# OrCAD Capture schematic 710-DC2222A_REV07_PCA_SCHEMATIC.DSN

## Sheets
1 PAGE3: size Custom; note: OVERSAMPLED 32-BIT ADC WITH PROGRAMMABLE DIGITAL FILTER
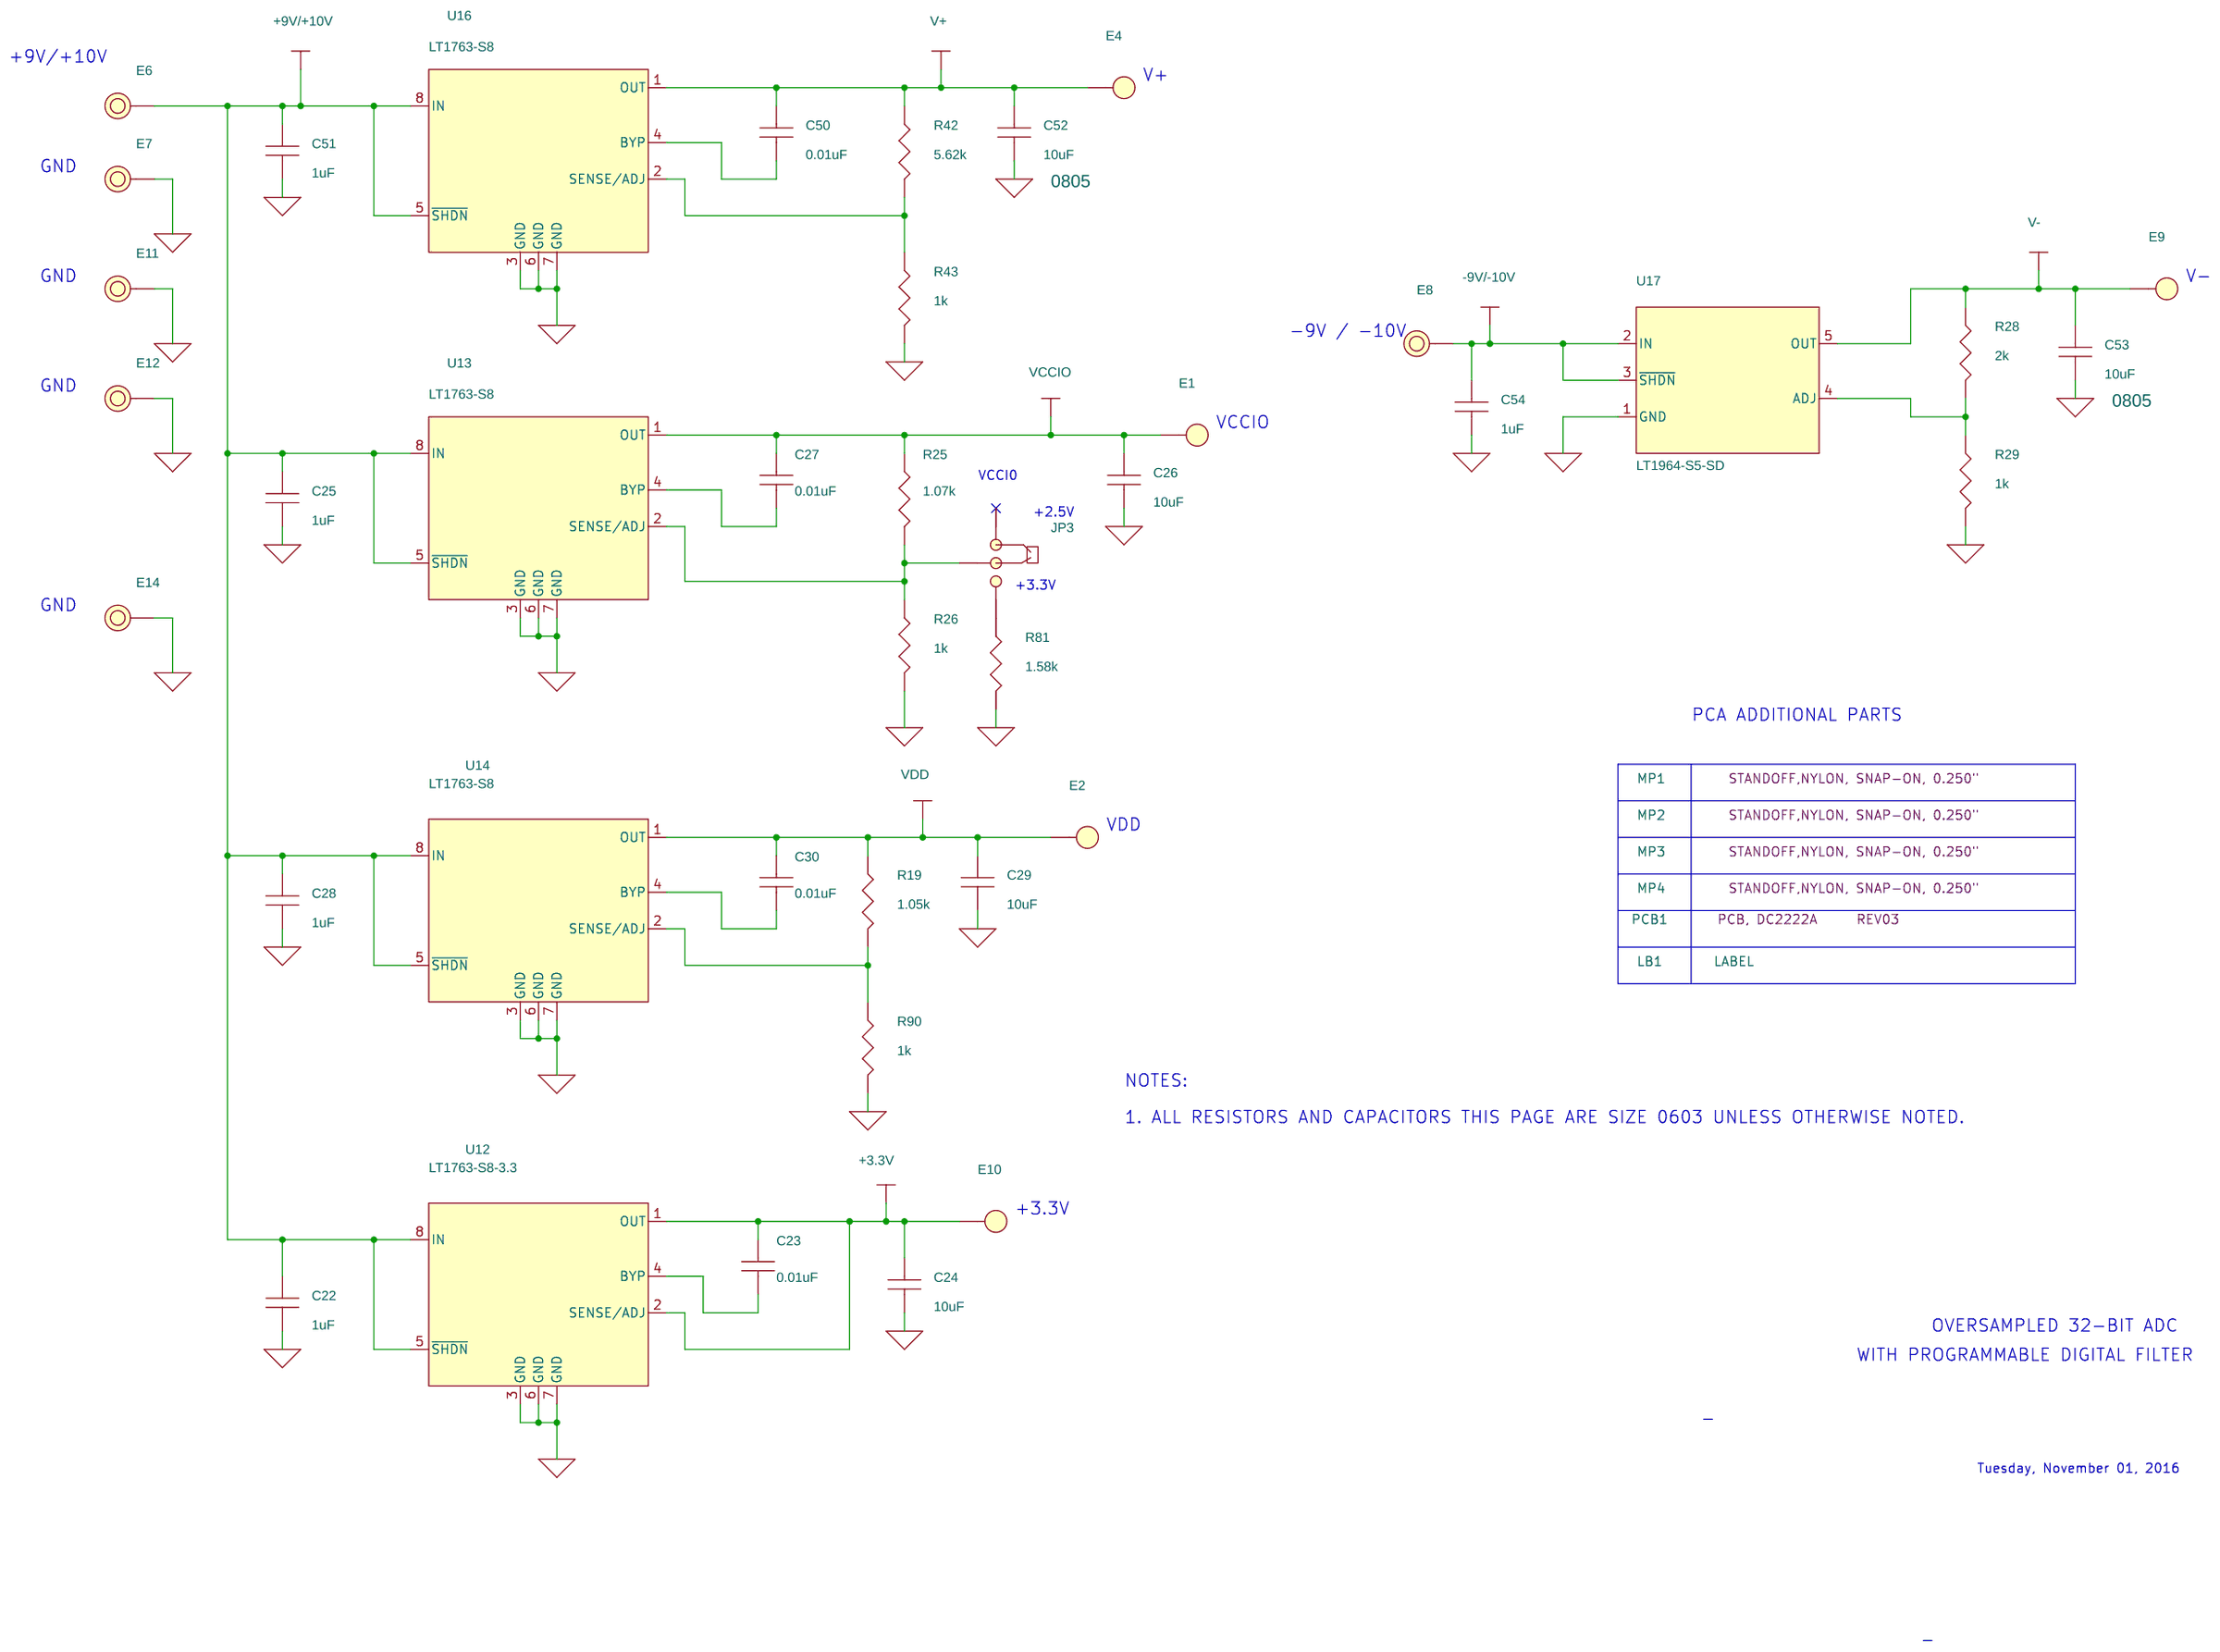
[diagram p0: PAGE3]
2 PAGE2: size Custom
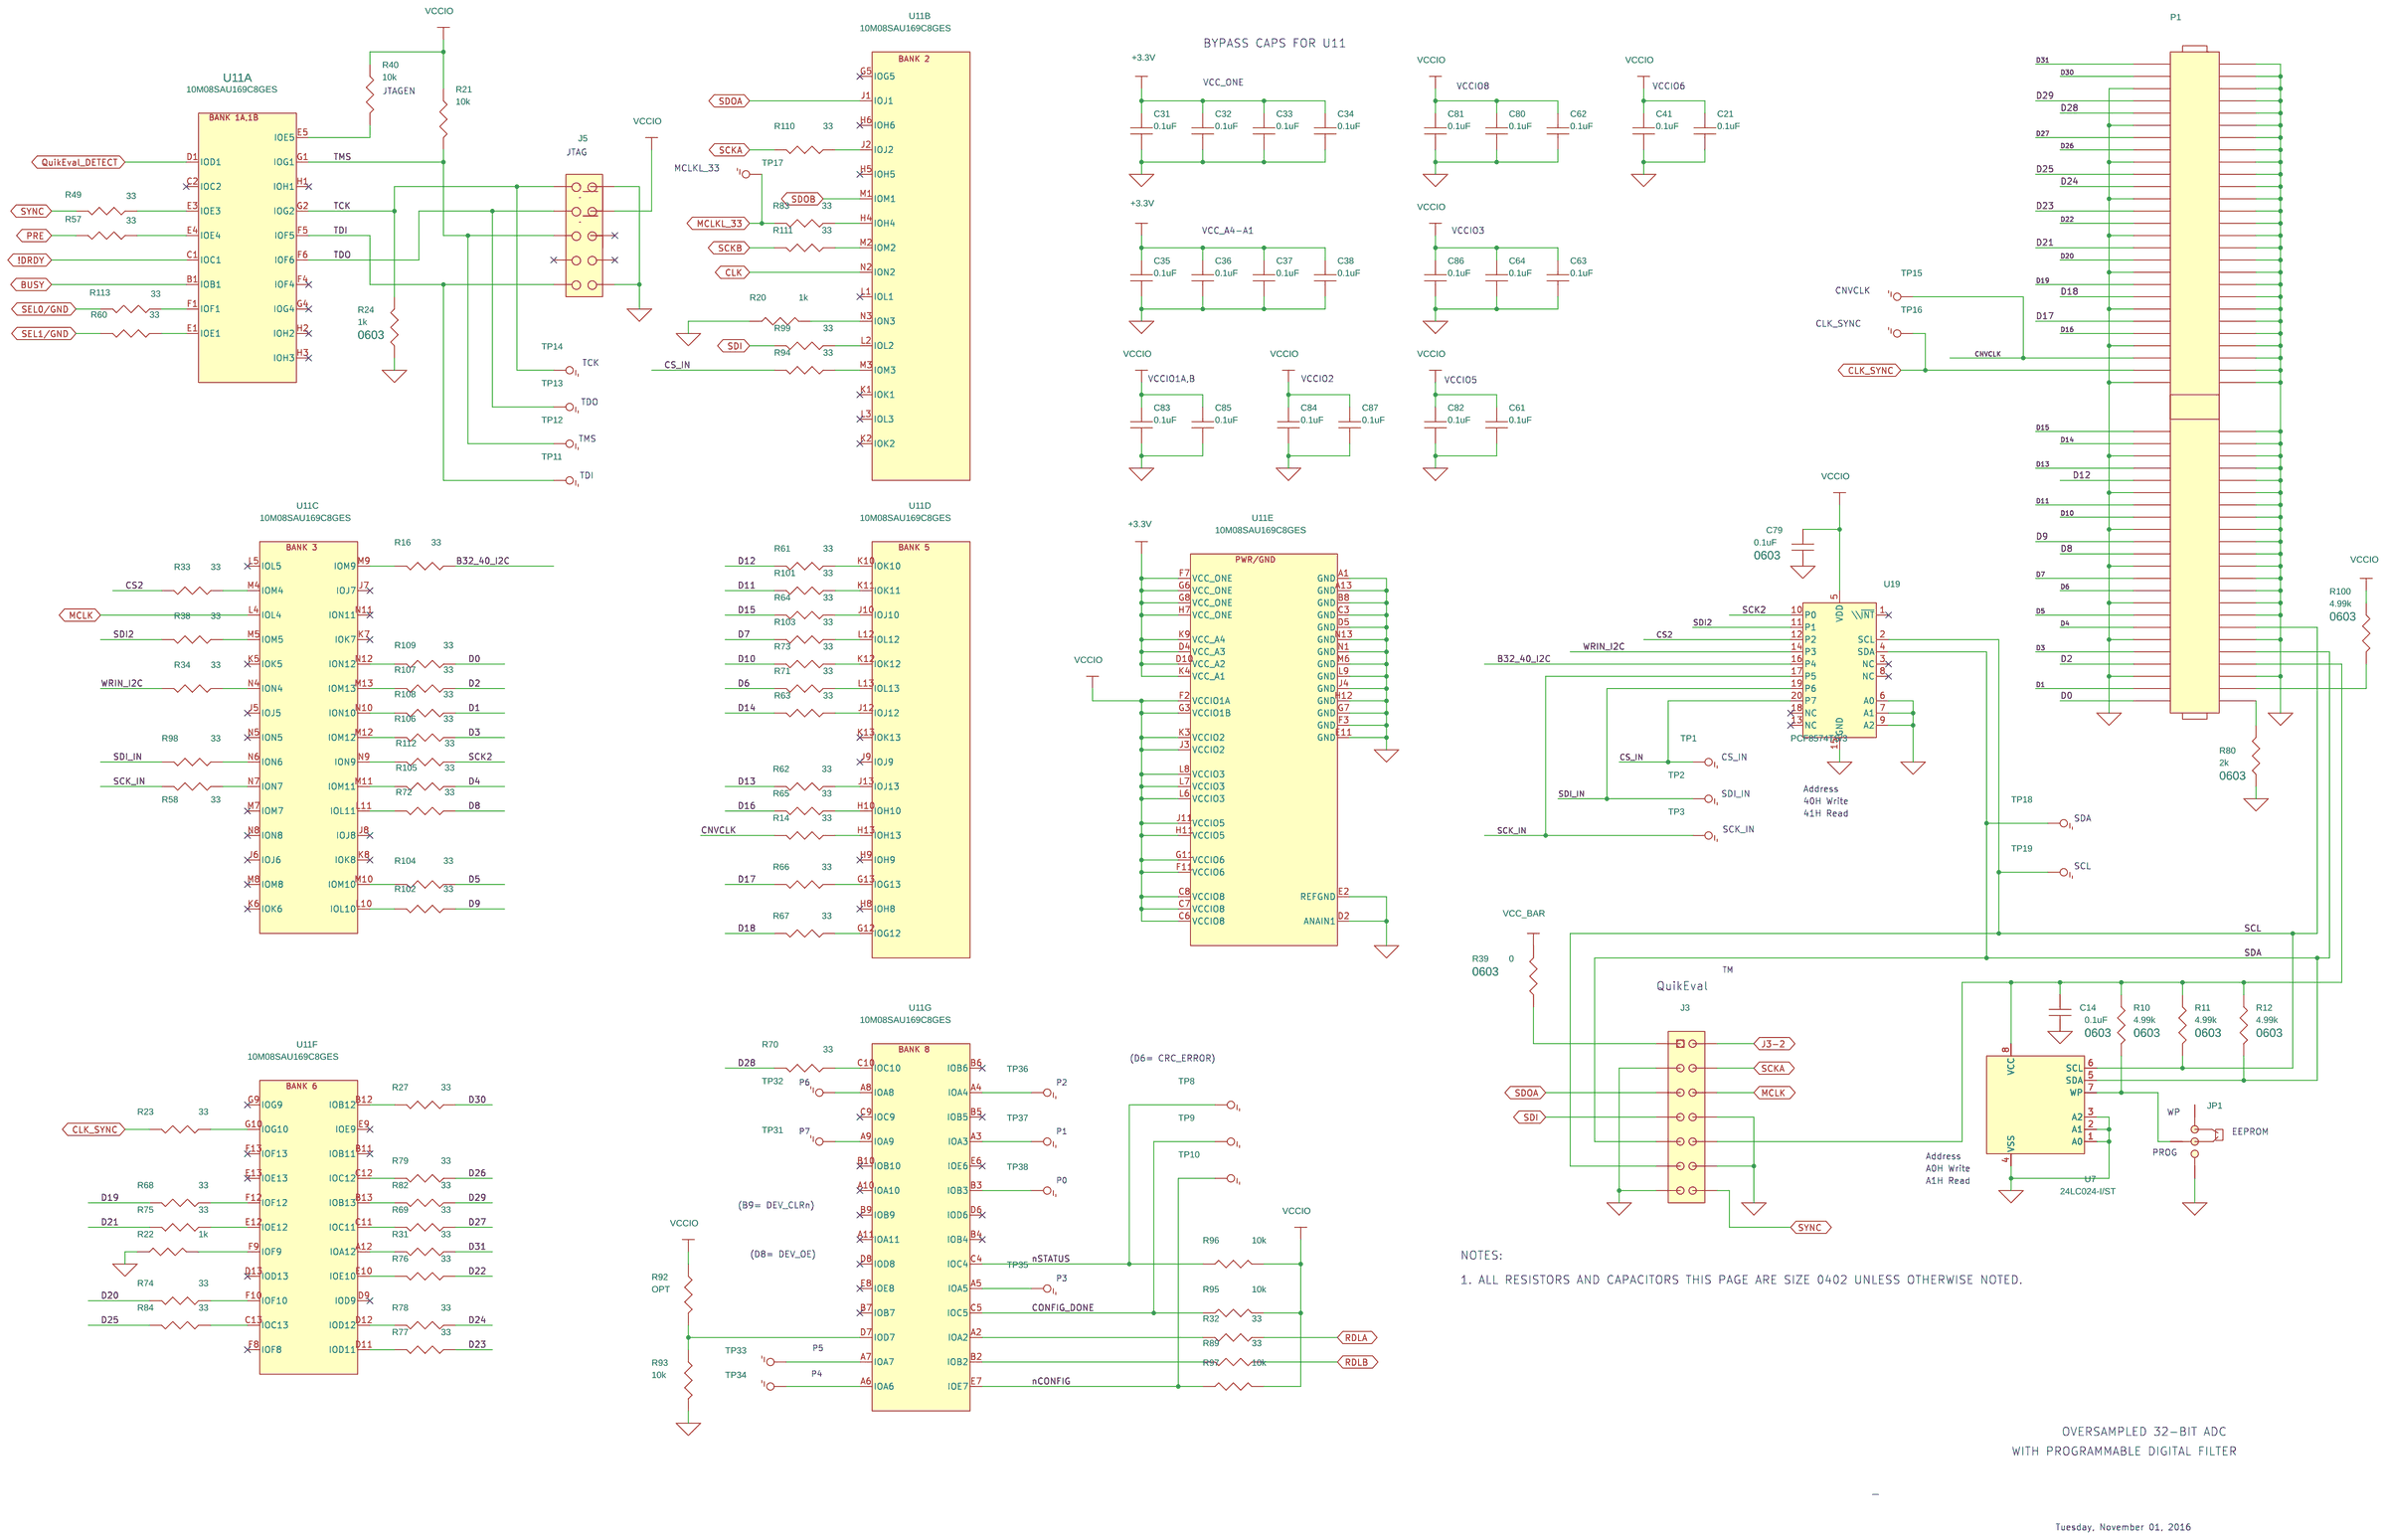
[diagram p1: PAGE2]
3 PAGE1: size Custom
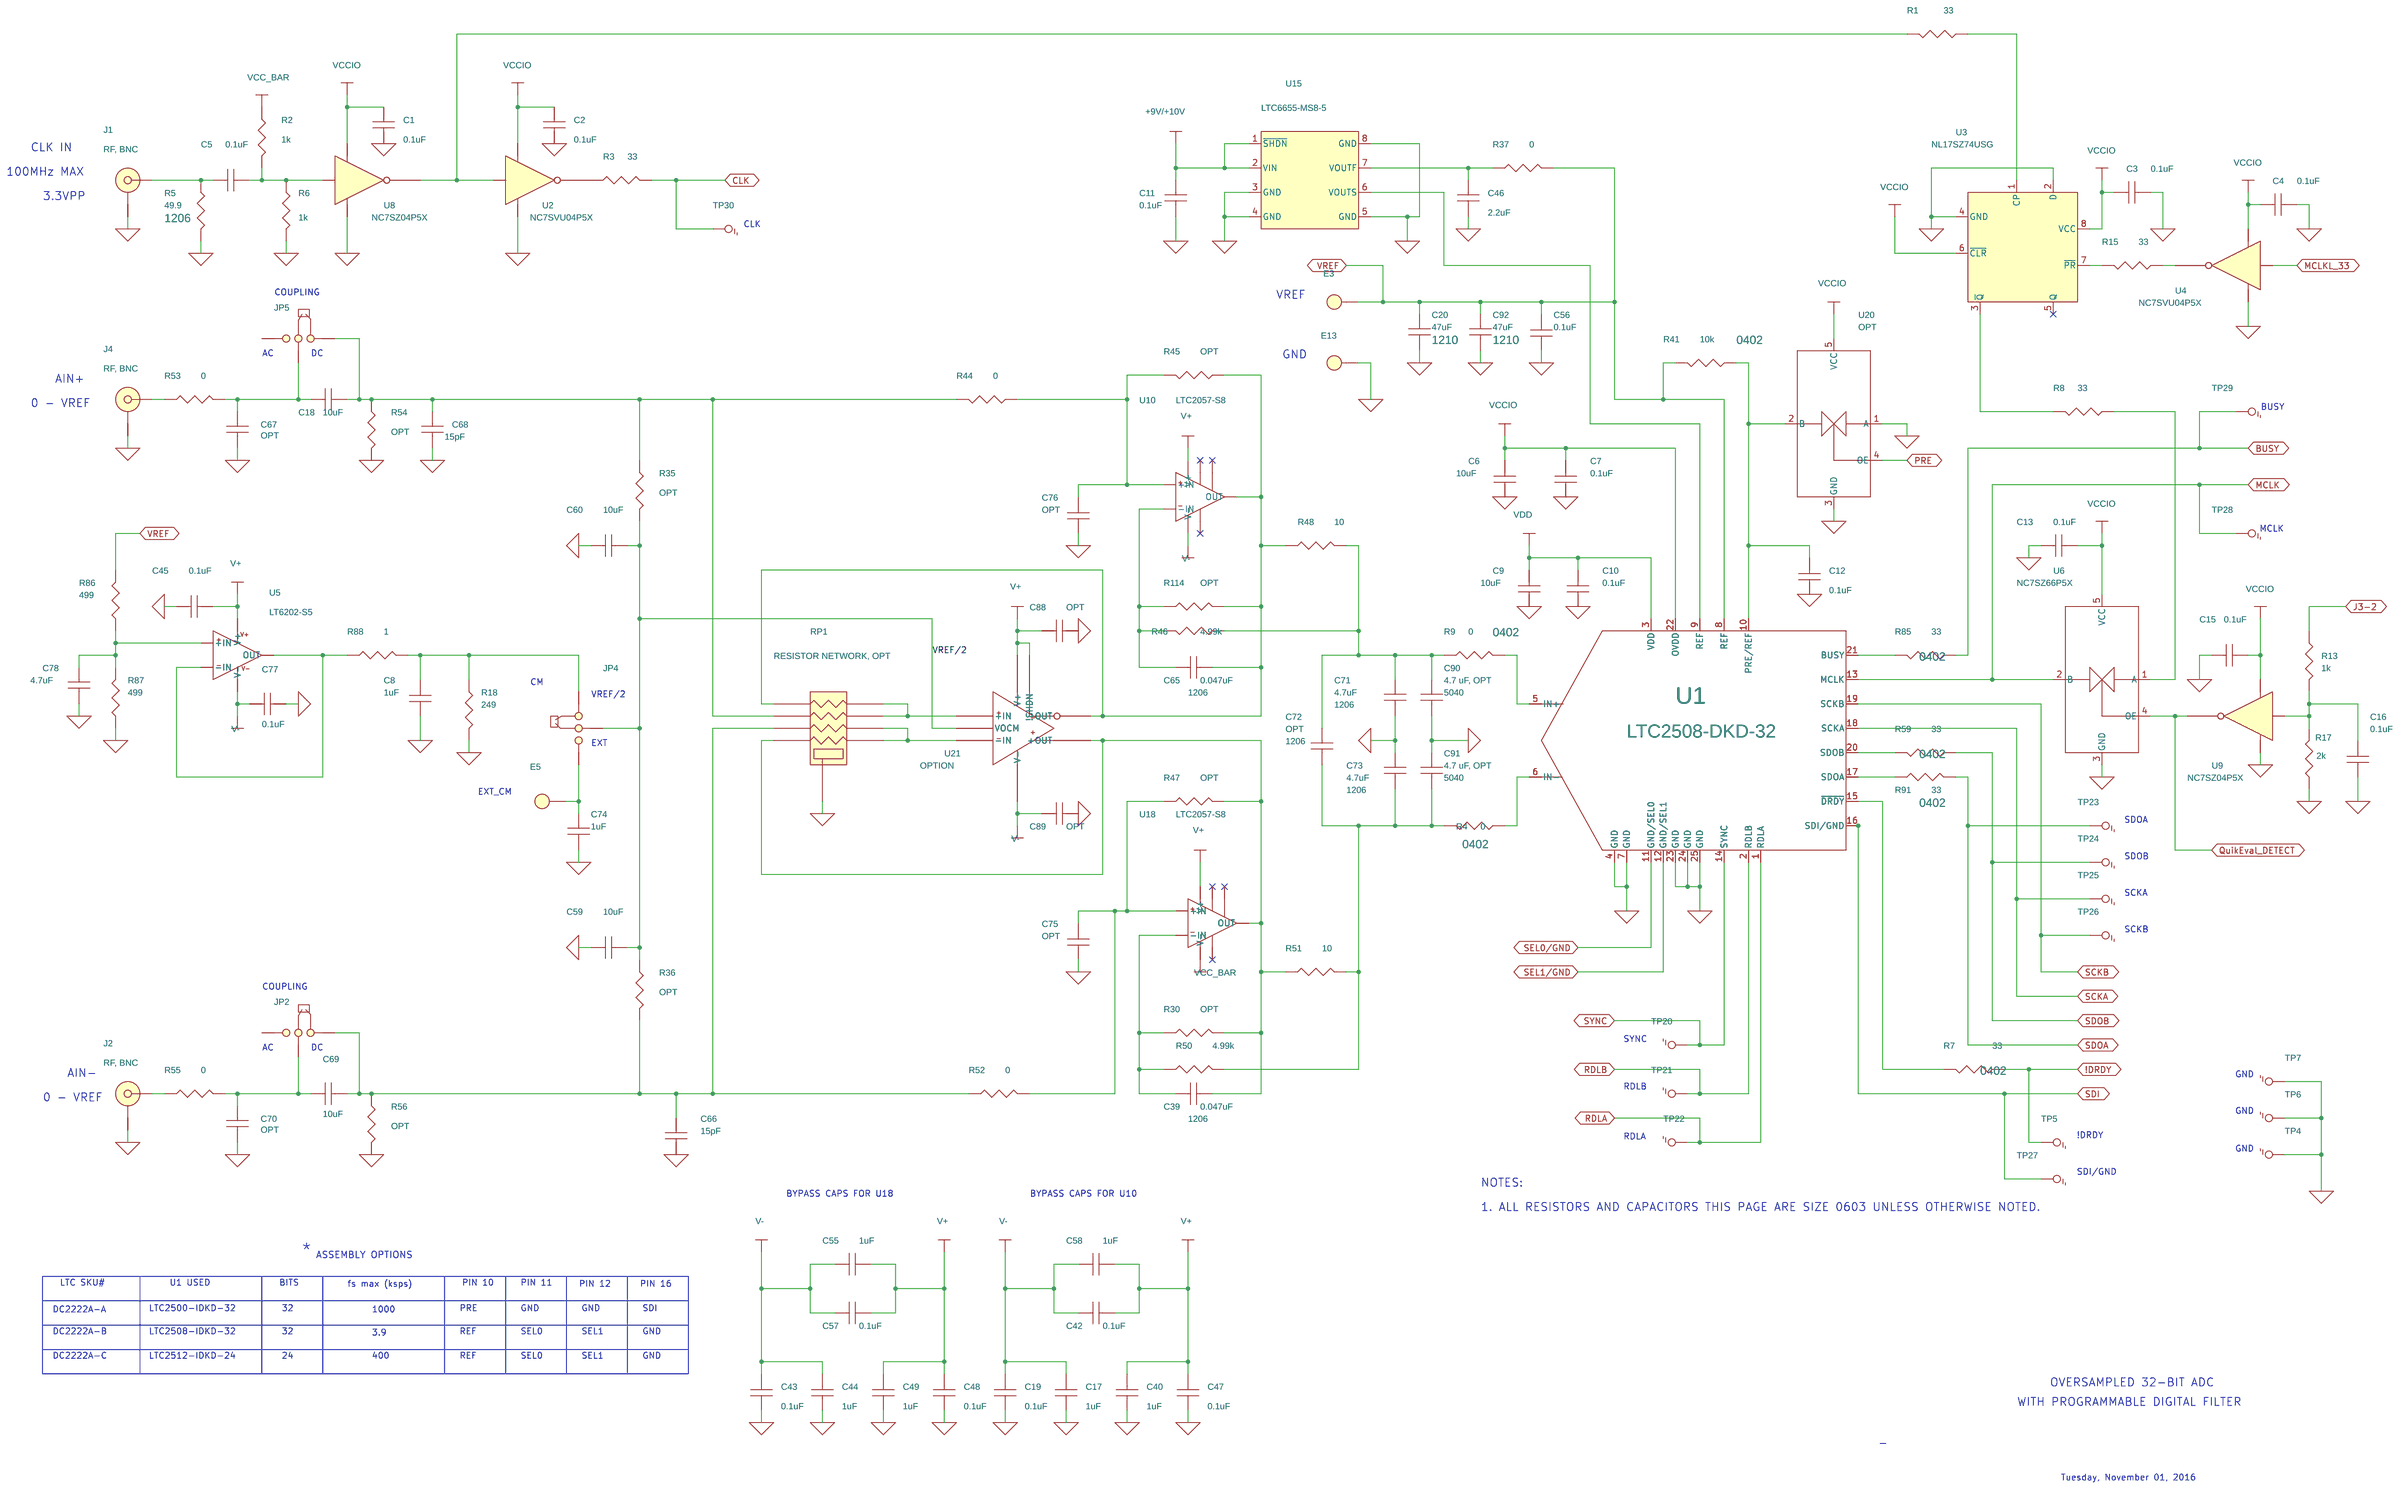
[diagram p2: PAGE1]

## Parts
sheet PAGE1
C1  0.1uF  [CC0603L]
C2  0.1uF  [CC0603L]
C3  0.1uF  [CC0603L]
C4  0.1uF  [CC0603L]
C5  0.1uF  [CC0603L]
C6  10uF  [CC0603L]
C7  0.1uF  [CC0603L]
C8  1uF  [CC0603L]
C9  10uF  [CC0603L]
C10  0.1uF  [CC0603L]
C11  0.1uF  [CC0603L]
C12  0.1uF  [CC0603L]
C13  0.1uF  [CC0603L]
C15  0.1uF  [CC0603L]
C16  0.1uF  [CC0603L]
C17  1uF  [CC0603N]
C18  10uF  [CC0603L]
C19  0.1uF  [CC0603N]
C20  47uF  [CC1210N]
C39  0.047uF  [CC1206N]
C40  1uF  [CC0603N]
C42  0.1uF  [CC0603N]
C43  0.1uF  [CC0603N]
C44  1uF  [CC0603N]
C45  0.1uF  [CC0603L]
C46  2.2uF  [CC0603L]
C47  0.1uF  [CC0603N]
C48  0.1uF  [CC0603N]
C49  1uF  [CC0603N]
C55  1uF  [CC0603N]
C56  0.1uF  [CC0603L]
C57  0.1uF  [CC0603N]
C58  1uF  [CC0603N]
C59  10uF  [CC0603N]
C60  10uF  [CC0603N]
C65  0.047uF  [CC1206N]
C66  15pF  [CC0603N]
C67  OPT  [CC1206N]
C68  15pF  [CC0603L]
C69  10uF  [CC0603L]
C70  OPT  [CC1206N]
C71  4.7uF  [CC1206N]
C72  OPT  [CC1206N]
C73  4.7uF  [CC1206N]
C74  1uF  [CC0603L]
C75  OPT  [CC0603N]
C76  OPT  [CC0603N]
C77  0.1uF  [CC0603L]
C78  4.7uF  [CC0603N]
C88  OPT  [CC0603L]
C89  OPT  [CC0603L]
C90  4.7 uF, OPT  [WIMA_5040]
C91  4.7 uF, OPT  [WIMA_5040]
C92  47uF  [CC1210N]
E3  TEST POINT  [MILLMAX2308]
E5  TEST POINT  [MILLMAX2308]
E13  TEST POINT  [MILLMAX2308]
J1  RF, BNC  [CONNEX-112404]
J2  RF, BNC  [CONNEX-112404]
J4  RF, BNC  [CONNEX-112404]
JP2  HDR.  [JP3X1/100]
JP4  HDR.  [JP3X1/100]
JP5  HDR.  [JP3X1/100]
R1  33  [CR0603L]
R2  1k  [CR0603L]
R3  33  [CR0603L]
R4  0  [CR0402L]
R5  49.9  [CR1206N]
R6  1k  [CR0603L]
R7  33  [CR0402L]
R8  33  [CR0603L]
R9  0  [CR0402L]
R13  1k  [CR0603L]
R15  33  [CR0603L]
R17  2k  [CR0603L]
R18  249  [CR0603L]
R30  OPT  [CR0603N]
R35  OPT  [CR0603N]
R36  OPT  [CR0603N]
R37  0  [CR0603L]
R41  10k  [CR0402N]
R44  0  [CR0603N]
R45  OPT  [CR0603N]
R46  4.99k  [CR0603N]
R47  OPT  [CR0603N]
R48  10  [CR0603N]
R50  4.99k  [CR0603N]
R51  10  [CR0603N]
R52  0  [CR0603N]
R53  0  [CR0603L]
R54  OPT  [CR0603N]
R55  0  [CR0603L]
R56  OPT  [CR0603N]
R59  33  [CR0402L]
R85  33  [CR0402L]
R86  499  [CR0603N]
R87  499  [CR0603N]
R88  1  [CR0603N]
R91  33  [CR0402L]
R114  OPT  [CR0603N]
RP1  RESISTOR NETWORK, OPT  [LTC-MS8E]
TP4  COPPER FEATURE PAD  [PADSTYLE1]
TP5  COPPER FEATURE PAD  [PADSTYLE1]
TP6  COPPER FEATURE PAD  [PADSTYLE1]
TP7  COPPER FEATURE PAD  [PADSTYLE1]
TP20  COPPER FEATURE PAD  [PADSTYLE1]
TP21  COPPER FEATURE PAD  [PADSTYLE1]
TP22  COPPER FEATURE PAD  [PADSTYLE1]
TP23  COPPER FEATURE PAD  [PADSTYLE1]
TP24  COPPER FEATURE PAD  [PADSTYLE1]
TP25  COPPER FEATURE PAD  [PADSTYLE1]
TP26  COPPER FEATURE PAD  [PADSTYLE1]
TP27  COPPER FEATURE PAD  [PADSTYLE1]
TP28  COPPER FEATURE PAD  [PADSTYLE1]
TP29  COPPER FEATURE PAD  [PADSTYLE1]
TP30  COPPER FEATURE PAD  [PADSTYLE1]
U1  LTC2508-DKD-32  [LTC-DKD-24-1864]
U2  NC7SVU04P5X  [SC70-5]
U3  NL17SZ74USG  [ONSEMI-US8]
U4  NC7SVU04P5X  [SC70-5]
U5  LT6202-S5  [LTC-S5-5-1635]
U6  NC7SZ66P5X  [SC70-5]
U8  NC7SZ04P5X  [SC70-5]
U9  NC7SZ04P5X  [SC70-5]
U10  LTC2057-S8  [LTC-S8-8-1610(S8)]
U15  LTC6655-MS8-5  [LTC-MS8-8-1660]
U18  LTC2057-S8  [LTC-S8-8-1610(S8)]
U20  OPT  [SC70-5]
U21  OPTION  [LTC-MS8-8-1660]
XJP2  SHUNT
XJP4  SHUNT
XJP5  SHUNT
sheet PAGE2
C14  0.1uF  [CC0603L]
C21  0.1uF  [CC0402L]
C31  0.1uF  [CC0402L]
C32  0.1uF  [CC0402L]
C33  0.1uF  [CC0402L]
C34  0.1uF  [CC0402L]
C35  0.1uF  [CC0402L]
C36  0.1uF  [CC0402L]
C37  0.1uF  [CC0402L]
C38  0.1uF  [CC0402L]
C41  0.1uF  [CC0402L]
C61  0.1uF  [CC0402L]
C62  0.1uF  [CC0402L]
C63  0.1uF  [CC0402L]
C64  0.1uF  [CC0402L]
C79  0.1uF  [CC0603L]
C80  0.1uF  [CC0402L]
C81  0.1uF  [CC0402L]
C82  0.1uF  [CC0402L]
C83  0.1uF  [CC0402L]
C84  0.1uF  [CC0402L]
C85  0.1uF  [CC0402L]
C86  0.1uF  [CC0402L]
C87  0.1uF  [CC0402L]
J3  HDR.  [HD2X7-079-MOLEX]
J5  HDR.  [SAMTEC_TSW-105-07-L-D]
JP1  HDR.  [JP3X1/100]
P1  EDGE-CON-100  [SMTC_EDG_CONN_100]
R10  4.99k  [CR0603L]
R11  4.99k  [CR0603L]
R12  4.99k  [CR0603L]
R14  33  [CR0402L]
R16  33  [CR0402L]
R20  1k  [CR0402L]
R21  10k  [CR0402L]
R22  1k  [CR0402L]
R23  33  [CR0402L]
R24  1k  [CR0603N]
R27  33  [CR0402L]
R31  33  [CR0402L]
R32  33  [CR0402L]
R33  33  [CR0402L]
R34  33  [CR0402L]
R38  33  [CR0402L]
R39  0  [CR0603N]
R40  10k  [CR0402L]
R49  33  [CR0402L]
R57  33  [CR0402L]
R58  33  [CR0402L]
R60  33  [CR0402L]
R61  33  [CR0402L]
R62  33  [CR0402L]
R63  33  [CR0402L]
R64  33  [CR0402L]
R65  33  [CR0402L]
R66  33  [CR0402L]
R67  33  [CR0402L]
R68  33  [CR0402L]
R69  33  [CR0402L]
R70  33  [CR0402L]
R71  33  [CR0402L]
R72  33  [CR0402L]
R73  33  [CR0402L]
R74  33  [CR0402L]
R75  33  [CR0402L]
R76  33  [CR0402L]
R77  33  [CR0402L]
R78  33  [CR0402L]
R79  33  [CR0402L]
R80  2k  [CR0603N]
R82  33  [CR0402L]
R83  33  [CR0402L]
R84  33  [CR0402L]
R89  33  [CR0402L]
R92  OPT  [CR0402N]
R93  10k  [CR0402N]
R94  33  [CR0402L]
R95  10k  [CR0402N]
R96  10k  [CR0402N]
R97  10k  [CR0402N]
R98  33  [CR0402L]
R99  33  [CR0402L]
R100  4.99k  [CR0603N]
R101  33  [CR0402L]
R102  33  [CR0402L]
R103  33  [CR0402L]
R104  33  [CR0402L]
R105  33  [CR0402L]
R106  33  [CR0402L]
R107  33  [CR0402L]
R108  33  [CR0402L]
R109  33  [CR0402L]
R110  33  [CR0402L]
R111  33  [CR0402L]
R112  33  [CR0402L]
R113  33  [CR0402L]
TP1  COPPER FEATURE PAD  [PADSTYLE1]
TP2  COPPER FEATURE PAD  [PADSTYLE1]
TP3  COPPER FEATURE PAD  [PADSTYLE1]
TP8  COPPER FEATURE PAD  [PADSTYLE1]
TP9  COPPER FEATURE PAD  [PADSTYLE1]
TP10  COPPER FEATURE PAD  [PADSTYLE1]
TP11  COPPER FEATURE PAD  [PADSTYLE1]
TP12  COPPER FEATURE PAD  [PADSTYLE1]
TP13  COPPER FEATURE PAD  [PADSTYLE1]
TP14  COPPER FEATURE PAD  [PADSTYLE1]
TP15  COPPER FEATURE PAD  [PADSTYLE1]
TP16  COPPER FEATURE PAD  [PADSTYLE1]
TP17  COPPER FEATURE PAD  [PADSTYLE1]
TP18  COPPER FEATURE PAD  [PADSTYLE1]
TP19  COPPER FEATURE PAD  [PADSTYLE1]
TP31  COPPER FEATURE PAD  [PADSTYLE1]
TP32  COPPER FEATURE PAD  [PADSTYLE1]
TP33  COPPER FEATURE PAD  [PADSTYLE1]
TP34  COPPER FEATURE PAD  [PADSTYLE1]
TP35  COPPER FEATURE PAD  [PADSTYLE1]
TP36  COPPER FEATURE PAD  [PADSTYLE1]
TP37  COPPER FEATURE PAD  [PADSTYLE1]
TP38  COPPER FEATURE PAD  [PADSTYLE1]
U7  24LC024-I/ST  [MICROCHIP-TSSOP-8]
U11  10M08SAU169C8GES  [ALTERA-169UBGA]  (sections A,B,C,D,E,F,G)
U19  PCF8574TS/3  [JEDEC-MO-152]
XJP1  SHUNT
sheet PAGE3
C22  1uF  [CC0603L]
C23  0.01uF  [CC0603L]
C24  10uF  [CC0603L]
C25  1uF  [CC0603L]
C26  10uF  [CC0603L]
C27  0.01uF  [CC0603L]
C28  1uF  [CC0603L]
C29  10uF  [CC0603L]
C30  0.01uF  [CC0603L]
C50  0.01uF  [CC0603L]
C51  1uF  [CC0603L]
C52  10uF  [CC0805N]
C53  10uF  [CC0805N]
C54  1uF  [CC0603L]
E1  TEST POINT  [MILLMAX2308]
E2  TEST POINT  [MILLMAX2308]
E4  TEST POINT  [MILLMAX2308]
E6  TEST POINT  [MILLMAX2501]
E7  TEST POINT  [MILLMAX2501]
E8  TEST POINT  [MILLMAX2501]
E9  TEST POINT  [MILLMAX2308]
E10  TEST POINT  [MILLMAX2308]
E11  TEST POINT  [MILLMAX2501]
E12  TEST POINT  [MILLMAX2501]
E14  TEST POINT  [MILLMAX2501]
JP3  HDR.  [JP3X1/100]
LB1  LABEL  [895-0154_REV01]
MP1  STANDOFF  [MTG-8831]
MP2  STANDOFF  [MTG-8831]
MP3  STANDOFF  [MTG-8831]
MP4  STANDOFF  [MTG-8831]
PCB1  PCB FABRICATION
R19  1.05k  [CR0603N]
R25  1.07k  [CR0603L]
R26  1k  [CR0603L]
R28  2k  [CR0603L]
R29  1k  [CR0603L]
R42  5.62k  [CR0603L]
R43  1k  [CR0603L]
R81  1.58k  [CR0603N]
R90  1k  [CR0603L]
U12  LT1763-S8-3.3  [LTC-S8-8-1610(S8)]
U13  LT1763-S8  [LTC-S8-8-1610(S8)]
U14  LT1763-S8  [LTC-S8-8-1610(S8)]
U16  LT1763-S8  [LTC-S8-8-1610(S8)]
U17  LT1964-S5-SD  [LTC-S5-5-1635]
XJP3  SHUNT

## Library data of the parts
C1-C5 C7 C10 C11 C13-C16 C56 C79 = CAP: CAP.,0.1uF,X7R,16V,10%,0603; CLASS: DISCRETE; Dielectric Type: X7R; FPLIST: CC0603N,CC0603L,CC0603M; Manufacturer: AVX; Manufacturer PN: 0603YC104KAT2A; PART_NUMBER: 150-0164; Package Size: 0603; Package Type: SMD; Rated Voltage: 16V; Tolerance: 10%
C6 C9 C18 C24 C26 C29 C69 = CAP: CAP.,10uF,X5R,6.3V,20%,0603; CLASS: DISCRETE; Dielectric Type: X5R; FPLIST: CC0603N,CC0603L,CC0603M; Manufacturer: AVX; Manufacturer PN: 06036D106MAT2A; PART_NUMBER: 150-3401; Package Size: 0603; Package Type: SMD; Rated Voltage: 6.3V; Tolerance: 20%
C8 = CAP: CAP.,1uF,X7R,16V,10%,0603; CLASS: DISCRETE; Dielectric Type: X7R; FPLIST: CC0603N,CC0603L,CC0603M; Manufacturer: AVX; Manufacturer PN: 0603YC105KAT2A; PART_NUMBER: 150-3384; Package Size: 0603; Package Type: SMD; Rated Voltage: 16V; Tolerance: 10%
C12 C19 C42 C43 C45 C47 C48 C57 C77 = CAP: CAP.,0.1uF,X7R,25V,20%,0603; CLASS: DISCRETE; Dielectric Type: X7R; FPLIST: CC0603N,CC0603L,CC0603M; Manufacturer: MURATA; Manufacturer PN: GRM188R71E104MA01D; PART_NUMBER: 150-3402; Package Size: 0603; Package Type: SMD; Rated Voltage: 25V; Tolerance: 20%
C17 C22 C25 C28 C40 C44 C49 C51 C54 C55 C58 C74 = CAP: CAP.,1uF,X7R,25V,10%,0603; CLASS: DISCRETE; Dielectric Type: X7R; FPLIST: CC0603N,CC0603L,CC0603M; Manufacturer: TDK; Manufacturer PN: C1608X7R1E105K080AB; PART_NUMBER: 150-3372; Package Size: 0603; Package Type: SMD; Rated Voltage: 25V; Tolerance: 10%
C20 C92 = CAP: CAP.,47uF,X7R,10V,10%,1210; CLASS: DISCRETE; Dielectric Type: X7R; Manufacturer: MURATA; Manufacturer PN: GRM32ER71A476KE15L; PART_NUMBER: 150-3403; Package Size: 1210; Package Type: SMD; Rated Voltage: 10V; Tolerance: 10%
C39 C65 = CAP: CAP.,0.047uF,C0G,50V,5%,1206; CLASS: DISCRETE; FPLIST: CC1206N,CC1206L,CC1206M; PART_NUMBER: 150-0469; Package Size: 1206; Package Type: Surface Mount, MLCC
C46 = CAP: CAP.,2.2uF,X5R,10V,10%,0603; CLASS: DISCRETE; Dielectric Type: X5R; FPLIST: CC0603N,CC0603L,CC0603M; Manufacturer: MURATA; Manufacturer PN: GRM188R61A225KE34D; PART_NUMBER: 150-0168; Package Size: 0603; Package Type: SMD; Rated Voltage: 10V; Tolerance: 10%
C59 C60 = CAP: CAP.,10uF,X5R,6.3V,20%,0603; CLASS: DISCRETE; Dielectric Type: X5R; Manufacturer: AVX; Manufacturer PN: 06036D106MAT2A; PART_NUMBER: 150-3401; Package Size: 0603; Package Type: SMD; Rated Voltage: 6.3V; Tolerance: 20%
C66 = CAP: CAP.,15pF,C0G,50V,10%,0603; CLASS: DISCRETE; Dielectric Type: C0G; Manufacturer: KEMET; Manufacturer PN: C0603C150K5GAC7867; PART_NUMBER: 150-3185; Package Size: 0603; Package Type: SMD; Rated Voltage: 50V; Tolerance: 10%
C67 C70 C72 = CAP: CAP., OPTION, 1206; CLASS: DISCRETE; FPLIST: CC1206N,CC1206L,CC1206M; PART_NUMBER: 150-3160; Package Size: 1206; Package Type: SMD
C68 = CAP: CAP.,15pF,C0G,50V,10%,0603; CLASS: DISCRETE; Dielectric Type: C0G; FPLIST: CC0603N,CC0603L,CC0603M; Manufacturer: KEMET; Manufacturer PN: C0603C150K5GAC7867; PART_NUMBER: 150-3185; Package Size: 0603; Package Type: SMD; Rated Voltage: 50V; Tolerance: 10%
C71 C73 = CAP: CAP.,4.7uF,X7R,25V,5%,1206; CLASS: DISCRETE; Dielectric Type: X7R; FPLIST: CC1206N,CC1206L,CC1206M; Manufacturer: Kemet; Manufacturer PN: C1206C475J3RACTU; PART_NUMBER: 150-0228; Package Size: 1206; Package Type: Surface Mount, MLCC; Rated Voltage: 25V; Tolerance: 5%
C75 C76 C88 C89 = CAP: CAP., OPTION, 0603; CLASS: DISCRETE; FPLIST: CC0603N,CC0603L,CC0603M; PART_NUMBER: 150-3038; Package Size: 0603; Package Type: SMD; UserField01: OPTION
C78 = CAP: CAP.,4.7uF,X5R,6.3V,20%,0603; CLASS: DISCRETE; Dielectric Type: X5R; Manufacturer: KEMET; Manufacturer PN: C0603C475M9PACTU; PART_NUMBER: 150-3141; Package Size: 0603; Package Type: SMD; Rated Voltage: 6.3V; Tolerance: 20%
C90 C91 = CAP: CAP., PET FILM, 63V 4.7uF 10%, 5040; BOM Notes: OPTIONAL; CLASS: DISCRETE; Manufacturer: WIMA; Manufacturer PN: SMDTC04470XA00KT00; PART_NUMBER: OPT-0046; Package Size: 5040; Package Type: SMD
E1-E5 E9 E10 E13 = TEST_POINT_.156_MILL-MAX_2308: TEST POINT,TURRET,0.064",MTG. HOLE; CLASS: IO; Manufacturer: MILL-MAX; Manufacturer PN: 2308-2-00-80-00-00-07-0; PART_NUMBER: 260-0004
J1 J2 J4 = BNC_50_OHM_112404_B: CONN.,RF, BNC,RCPT,THT, STR,5-PIN; CLASS: IO; Manufacturer: AMPHENOL CONNEX; Manufacturer PN: 112404; PART_NUMBER: 250-0427
JP1-JP5 = 3_PIN_HEADER_.100_SINGLE_ROW: CONN.,HDR.,MALE,1x3,2.54mm,THT, STR; CLASS: IO; Manufacturer: SAMTEC; Manufacturer PN: TSW-103-07-L-S; PART_NUMBER: 250-0361
R1 R3 R8 R15 = RES: RES.,33 OHMS,5%,1/10W,0603; CLASS: DISCRETE; FPLIST: CR0603N,CR0603L,CR0603M; Manufacturer: YAGEO; Manufacturer PN: RC0603JR-0733RL; PART_NUMBER: 100-0004; Package Size: 0603; Rated Power: 1/10W; Temperature Coefficient: 100ppm/C; Tolerance: 5%
R2 R6 R13 = RES: RES.,1k OHM,1%,1/10W,0603; CLASS: DISCRETE; FPLIST: CR0603N,CR0603L,CR0603M; Manufacturer: NIC; Manufacturer PN: NRC06F1001TRF; PART_NUMBER: 100-2422; Package Size: 0603; Rated Power: 1/10W; Temperature Coefficient: 100ppm; Tolerance: 1%
R4 R9 = RES: RES.,0 OHM,1/16W,0402; CLASS: DISCRETE; FPLIST: CR0402N,CR0402L,CR0402M; Manufacturer: ROHM; Manufacturer PN: MCR01MZPJ000; PART_NUMBER: 100-0025; Package Size: 0402; Rated Power: 1/16W
R5 = RES: RES.,49.9 OHMS,1%,1/4W,1206; CLASS: DISCRETE; Manufacturer: NIC; Manufacturer PN: NRC12F49R9TRF; PART_NUMBER: 100-2791; Package Size: 1206; Rated Power: 1/4W; Temperature Coefficient: 100ppm/C; Tolerance: 1%
R7 R14 R16 R23 R27 R31-R34 R38 R49 R57-R79 R82-R85 R89 R91 R94 R98 R99 R101-R113 = RES: RES.,33 OHMS,5%,1/16W,0402; CLASS: DISCRETE; FPLIST: CR0402N,CR0402L,CR0402M; Manufacturer: NIC; Manufacturer PN: NRC04J330TRF; PART_NUMBER: 100-2624; Package Size: 0402; Rated Power: 1/16W; Temperature Coefficient: 200ppm; Tolerance: 5%
R17 = RES: RES.,2k OHMS,5%,1/10W,0603; CLASS: DISCRETE; FPLIST: CR0603N,CR0603L,CR0603M; Manufacturer: YAGEO; Manufacturer PN: RC0603JR-072KL; PART_NUMBER: 100-2792; Package Size: 0603; Rated Power: 1/10W; Temperature Coefficient: 100ppm/C; Tolerance: 5%
R18 = RES: RES.,249 OHMS,1%,1/10W,0603; CLASS: DISCRETE; FPLIST: CR0603N,CR0603L,CR0603M; Manufacturer: NIC; Manufacturer PN: NRC06F2490TRF; PART_NUMBER: 100-2587; Package Size: 0603; Rated Power: 1/10W; Temperature Coefficient: 100ppm/C; Tolerance: 1%
R30 R35 R36 R45 R47 R54 R56 R114 = RES: RES., OPTION, 0603; CLASS: DISCRETE; FPLIST: CR0603N,CR0603L,CR0603M; PART_NUMBER: 100-2374; Package Size: 0603
R37 R53 R55 = RES: RES.,0 OHM,1/10W,0603; CLASS: DISCRETE; FPLIST: CR0603N,CR0603L,CR0603M; Manufacturer: VISHAY; Manufacturer PN: CRCW06030000Z0EA; PART_NUMBER: 100-0009; Package Size: 0603; Rated Power: 1/10W
R41 = RES: RES.,10k OHMS,5%,1/16W,0402; CLASS: DISCRETE; Manufacturer: YAGEO; Manufacturer PN: RC0402JR-0710KL; PART_NUMBER: 100-0023; Package Size: 0402; Rated Power: 1/16W; Temperature Coefficient: 100ppm; Tolerance: 5%
R44 R52 = RES: RES.,0 OHMS,1/10W,0603; CLASS: DISCRETE; FPLIST: CR0603N,CR0603L,CR0603M; Manufacturer: PANASONIC; Manufacturer PN: ERJ3GEY0R00V; PART_NUMBER: 100-0204; Package Size: 0603; Rated Power: 1/10W
R46 R50 = RES: RES.,4.99k OHMS,1%,1/10W,0603; CLASS: DISCRETE; FPLIST: CR0603N,CR0603L,CR0603M; PART_NUMBER: 100-0121; Package Size: 0603
R48 R51 = RES: RES.,10 OHMS,1%,1/10W,0603; CLASS: DISCRETE; FPLIST: CR0603N,CR0603L,CR0603M; Manufacturer: PANASONIC; Manufacturer PN: ERJ3EKF10R0V; PART_NUMBER: 100-2306; Package Size: 0603; Rated Power: 1/10W; Temperature Coefficient: 100ppm/C; Tolerance: 1%
R86 R87 = RES: RES.,499 OHMS,1%,1/10W,0603; CLASS: DISCRETE; Manufacturer: PANASONIC; Manufacturer PN: ERJ3EKF4990V; PART_NUMBER: 100-2777; Package Size: 0603; Rated Power: 1/10W; Temperature Coefficient: 100ppm/C; Tolerance: 1%
R88 = RES: RES.,1 OHM,5%,1/10W,0603; CLASS: DISCRETE; Manufacturer: PANASONIC; Manufacturer PN: ERJ3GEYJ1R0V; PART_NUMBER: 100-0149; Package Size: 0603; Rated Power: 1/10W; Temperature Coefficient: 100ppm/C; Tolerance: 5%
RP1 = LT5400-MS8E-X: QUAD MATCHED RESISTOR NETWORK, MS8E; CLASS: IC; Manufacturer: OPTION; Manufacturer PN: OPTION; PART_NUMBER: OPT-0044; Package Size: MS8E; Package Type: MS8E
TP1-TP38 = PAD_SMALL_FILLED: TESTPOINT, PCB COPPER FEATURE; CLASS: IO; FPLIST: PADSTYLE1,PADSTYLE2,PADSTYLE3,PADSTYLE4,PADSTYLE5,PADSTYLE6,PADSTYLE7,PADSTYLE8; Manufacturer: N/A; Manufacturer PN: N/A; PART_NUMBER: PCBPADS-11
U1 = LTC2500_2508_2512-DKD-X: IC,ADC W/PRGM. DIG. FILTER, 32BIT,24 LEAD QFN; CLASS: IC; Manufacturer: LINEAR TECHNOLOGY; Manufacturer PN: LTC2508IDKD-32#PBF; PART_NUMBER: LTC2508IDKD-32#PBF; Package Type: 24 LEAD QFN
U2 U4 = NC7SVU04P5X-SC70-5_B: IC,ULP-A UNBUFFERED INVERTER,SC70-5; CLASS: IC; Manufacturer: FAIRCHILD SEMI; PART_NUMBER: 280-0491
U3 = NL17SZ74_B: IC,Single D Flip Flop,US8,Case 493; CLASS: IC; Manufacturer: ON Semiconductor; PART_NUMBER: 280-0490; Package Size: US8; Package Type: US8
U5 = LT6202-S5: IC,OP-AMP, LOW NOISE,TSOT23-5; CLASS: IC; Manufacturer: LINEAR TECHNOLOGY; Manufacturer PN: LT6202CS5#PBF; PART_NUMBER: LT6202CS5#PBF; Package Size: S5; Package Type: TSOT23-5
U6 = NC7SZ66P5X: IC,Single SPST Bus Switch,SC70-5; CLASS: IC; Manufacturer: FAIRCHILD SEMI; PART_NUMBER: 280-0493
U8 U9 = NC7SZ04P5X-SC70-5_B: IC,TinyLogic UHS Inverter,SC70-5; CLASS: IC; Manufacturer: FAIRCHILD SEMI; PART_NUMBER: 280-0495
U10 U18 = GENERIC-SINGLE_OP-AMP_B: IC,OP-AMP, LOW NOISE,SOIC,HI VOLTAGE, ZERO DRIFT; CLASS: IC; Manufacturer: LINEAR TECHNOLOGY; Manufacturer PN: LTC2057IS8#PBF; PART_NUMBER: LTC2057IS8#PBF; Package Size: SO-8; Package Type: SOIC
U15 = LTC6655-MS8-X: IC,Low Drift Precision Reference,MSOP-8,5V, 0.25ppm Noise; CLASS: IC; Manufacturer: LINEAR TECHNOLOGY; Manufacturer PN: LTC6655BHMS8-5#PBF; PART_NUMBER: LTC6655BHMS8-5#PBF; Package Size: MS8; Package Type: MSOP-8
U20 = NC7SZ66P5X: IC,SPST Bus Switch,SC70-5-OPTION; CLASS: IC; Manufacturer: FAIRCHILD SEMI; Manufacturer PN: OPTION-NC7SZ66P5X; PART_NUMBER: OPT-0045
U21 = LTC6363-MS8: IC, DIFF AMP, OPTION, MSOP; CLASS: IC; PART_NUMBER: OPT-0043; Package Size: MSOP
XJP1-XJP5 = SHUNT_.100: CONN.,SHUNT,FEMALE,2 POS,2.54mm; CLASS: IO; Manufacturer: SAMTEC; Manufacturer PN: SNT-100-BK-G; PART_NUMBER: 250-0036
C21 C31-C38 C41 C61-C64 C80-C87 = CAP: CAP.,0.1uF,X7R,16V,10%,0402; CLASS: DISCRETE; Dielectric Type: X7R; FPLIST: CC0402N,CC0402L,CC0402M; Manufacturer: AVX; Manufacturer PN: 0402YC104KAT2A; PART_NUMBER: 150-3065; Package Size: 0402; Package Type: SMD; Rated Voltage: 16V; Tolerance: 10%
J3 = CONN_2X7_.079_MOLEX_RIBBON_C: CONN.,HDR.,MALE,2x7,2mm,THT, VERT,SHROUDED; CLASS: IO; Manufacturer: MOLEX; Manufacturer PN: 87831-1420; PART_NUMBER: 250-0403
J5 = HEADER_2X5_.100: CONN.,HDR.,MALE,2x5,2.54mm,THT, STR,MATTE TIN ON TAIL; CLASS: IO; Manufacturer: SAMTEC; Manufacturer PN: TSW-105-07-L-D; PART_NUMBER: 250-0518
P1 = CON-EDGE-FOR_DC890: PCB COPPER FEATURE- DC890 EDGE CONN.; CLASS: IO; PART_NUMBER: PCBEDGECONN-2
R10-R12 = RES: RES.,4.99k OHMS,1%,1/10W,0603; CLASS: DISCRETE; FPLIST: CR0603N,CR0603L,CR0603M; Manufacturer: NIC; Manufacturer PN: NRC06F4991TRF; PART_NUMBER: 100-2510; Package Size: 0603; Rated Power: 1/10W; Temperature Coefficient: 100ppm; Tolerance: 1%
R20 R22 = RES: RES.,1k OHMS,5%,1/16W,0402; CLASS: DISCRETE; FPLIST: CR0402N,CR0402L,CR0402M; Manufacturer: ROHM; Manufacturer PN: MCR01MZPF1001; PART_NUMBER: 100-0091; Package Size: 0402; Rated Power: 1/16W; Temperature Coefficient: 100ppm/C; Tolerance: 5%
R21 R40 R93 R95-R97 = RES: RES.,10k OHMS,5%,1/16W,0402; CLASS: DISCRETE; FPLIST: CR0402N,CR0402L,CR0402M; Manufacturer: YAGEO; Manufacturer PN: RC0402JR-0710KL; PART_NUMBER: 100-0023; Package Size: 0402; Rated Power: 1/16W; Temperature Coefficient: 100ppm; Tolerance: 5%
R24 = RES: RES.,1k OHM,1%,1/10W,0603; CLASS: DISCRETE; Manufacturer: NIC; Manufacturer PN: NRC06F1001TRF; PART_NUMBER: 100-2422; Package Size: 0603; Rated Power: 1/10W; Temperature Coefficient: 100ppm; Tolerance: 1%
R39 = RES: RES.,0 OHM,1/10W,0603; CLASS: DISCRETE; Manufacturer: VISHAY; Manufacturer PN: CRCW06030000Z0EA; PART_NUMBER: 100-0009; Package Size: 0603; Rated Power: 1/10W
R80 = RES: RES.,2k OHMS,1%,1/10W,0603; CLASS: DISCRETE; Manufacturer: NIC; Manufacturer PN: NRC06F2001TRF; PART_NUMBER: 100-2313; Package Size: 0603; Rated Power: 1/10W; Temperature Coefficient: 100ppm/C; Tolerance: 1%
R92 = RES: RES., OPTION, 0402; CLASS: DISCRETE; FPLIST: CR0402N,CR0402L,CR0402M; PART_NUMBER: 100-0357; Package Size: 0402
R100 = RES: RES.,4.99k OHMS,1%,1/10W,0603; CLASS: DISCRETE; Manufacturer: NIC; Manufacturer PN: NRC06F4991TRF; PART_NUMBER: 100-2510; Package Size: 0603; Rated Power: 1/10W; Temperature Coefficient: 100ppm; Tolerance: 1%
U7 = 24LC024-I_ST_TSSOP-8: IC,EEPROM, I2C,TSSOP-8,2Kb (256 x 8), 400kHz; CLASS: IC; Manufacturer: MICROCHIP; PART_NUMBER: 280-0494; Package Size: TSSOP-8; Package Type: TSSOP-8
U11 = 10M08SAU169C8GES: IC,FPGA, MAX 10, 8000 CELLS,169 PIN UFBGA; CLASS: IC; Manufacturer: ALTERA; PART_NUMBER: 280-0550; Package Type: 169 PIN UFBGA
U19 = PCF8574-SSOP20: IC,REMOTE 8-BIT I/O EXPANDER,SSOP-20; CLASS: IC; Manufacturer: NXP SEMICONDUCTORS; Manufacturer PN: PCF8574TS/3,112; PART_NUMBER: 280-0502; Package Size: JEDEC MO-152; Package Type: SSOP-20
C23 C27 C30 C50 = CAP: CAP.,0.01uF,X7R,25V,10%,0603; CLASS: DISCRETE; Dielectric Type: X7R; FPLIST: CC0603N,CC0603L,CC0603M; Manufacturer: AVX; Manufacturer PN: 06033C103KAT2A; PART_NUMBER: 150-3341; Package Size: 0603; Package Type: SMD; Rated Voltage: 25V; Tolerance: 10%
C52 C53 = CAP: CAP.,10uF,X5R,25V,10%,0805; CLASS: DISCRETE; Dielectric Type: X5R; Manufacturer: MURATA; Manufacturer PN: GRM21BR61E106KA73L; PART_NUMBER: 150-3405; Package Size: 0805; Package Type: SMD; Rated Voltage: 25V; Tolerance: 10%; UserField01: Thickness = 1.25 +/-0.15mm
E6-E8 E11 E12 E14 = TESTPOINT_.219_MILL-MAX_2501: TEST POINT,TURRET,0.094",MTG. HOLE; CLASS: IO; Manufacturer: MILL-MAX; Manufacturer PN: 2501-2-00-80-00-00-07-0; PART_NUMBER: 260-0003
LB1 = BLANK_LABEL: LABEL SPEC, DEMO BOARD SERIAL NUMBER; Manufacturer: BRADY; Manufacturer PN: THT-96-717-10; PART_NUMBER: 895-0154
MP1-MP4 = BLANK_MECHANICAL_PART: STANDOFF,NYLON, SNAP-ON, 0.250"; CLASS: MECHANICAL PART; Manufacturer: KEYSTONE; Manufacturer PN: 8831; PART_NUMBER: 763-0006
PCB1 = BLANK_PCB_PART: PCB, DC2222A; BOM Notes: REV03; CLASS: PCB; Manufacturer: MAO BANG ELECTRONICS; Manufacturer PN: 600-DC2222A; PART_NUMBER: 600-DC2222A
R19 = RES: RES.,1.05K OHMS,1%,1/10W,0603; CLASS: DISCRETE; Manufacturer: PANASONIC; Manufacturer PN: ERJ3EKF1051V; PART_NUMBER: 100-0402; Package Size: 0603; Rated Power: 1/10W; Temperature Coefficient: 100ppm; Tolerance: 1%
R25 = RES: RES.,1.07k OHMS,1%,1/10W,0603; CLASS: DISCRETE; FPLIST: CR0603N,CR0603L,CR0603M; Manufacturer: VISHAY; Manufacturer PN: CRCW06031K07FKEA; PART_NUMBER: 100-0403; Package Size: 0603; Rated Power: 1/10W; Tolerance: 1%
R26 R29 R43 R90 = RES: RES.,1k OHMS,5%,1/10W,0603; CLASS: DISCRETE; FPLIST: CR0603N,CR0603L,CR0603M; Manufacturer: SAMSUNG; Manufacturer PN: RC1608J102CS; PART_NUMBER: 100-0020; Package Size: 0603; Rated Power: 1/10W; Temperature Coefficient: 100ppm/C; Tolerance: 5%
R28 = RES: RES.,2k OHMS,1%,1/10W,0603; CLASS: DISCRETE; FPLIST: CR0603N,CR0603L,CR0603M; Manufacturer: NIC; Manufacturer PN: NRC06F2001TRF; PART_NUMBER: 100-2313; Package Size: 0603; Rated Power: 1/10W; Temperature Coefficient: 100ppm/C; Tolerance: 1%
R42 = RES: RES.,5.62k OHMS,1%,1/10W,0603; CLASS: DISCRETE; FPLIST: CR0603N,CR0603L,CR0603M; Manufacturer: VISHAY; Manufacturer PN: CRCW06035K62FKEA; PART_NUMBER: 100-2795; Package Size: 0603; Rated Power: 1/10W; Temperature Coefficient: 100ppm; Tolerance: 1%
R81 = RES: RES.,1.58k OHMS,1%,1/10W,0603; CLASS: DISCRETE; Manufacturer: VISHAY; Manufacturer PN: CRCW06031K58FKEA; PART_NUMBER: 100-0404; Package Size: 0603; Rated Power: 1/10W; Tolerance: 1%
U12 = LT1763-S8-X_ALT2: IC,LOW NOISE, LDO MICROPOWER REG.,SO-8,3.3V, 0.5A; CLASS: IC; Manufacturer: LINEAR TECHNOLOGY; Manufacturer PN: LT1763CS8-3.3#PBF; PART_NUMBER: LT1763CS8-3.3#PBF; Package Size: SO8; Package Type: SO-8
U13 U14 U16 = LT1763-S8-X_ALT2: IC,LDO Micropower Reg. ADJ.,SO-8,500mA; CLASS: IC; Manufacturer: LINEAR TECHNOLOGY; Manufacturer PN: LT1763CS8#PBF; PART_NUMBER: LT1763CS8#PBF; Package Size: LTC-S8; Package Type: SO-8
U17 = LT1964-S5-SD: IC,LDO Neg. Micropower Regulator,SOT23-5,200mA, 5V; CLASS: IC; Manufacturer: LINEAR TECHNOLOGY; Manufacturer PN: LT1964ES5-SD#PBF; PART_NUMBER: LT1964ES5-SD#PBF; Package Size: SOT23-5; Package Type: SOT23-5

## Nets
+3.3V: C23.1 C24.1 C31.1 C32.1 C33.1 C34.1 C35.1 C36.1 C37.1 C38.1 E10.1(A) U11.D4(VCC_A3) U11.D10(VCC_A2) U11.F7(VCC_ONE) U11.G6(VCC_ONE) U11.G8(VCC_ONE) U11.H7(VCC_ONE) U11.K4(VCC_A1) U11.K9(VCC_A4) U12.1(OUT) U12.2(SENSE/ADJ)
+9V/+10V: C11.1 C22.1 C25.1 C28.1 C51.1 E6.1 R39.2 U12.5(~{SHDN}) U12.8(IN) U13.5(~{SHDN}) U13.8(IN) U14.5(~{SHDN}) U14.8(IN) U15.1(~{SHDN}) U15.2(VIN) U16.5(~{SHDN}) U16.8(IN)
-9V/-10V: C54.1 E8.1 U17.2(IN) U17.3(~{SHDN})
GND: C1.2 C2.2 C3.2 C4.2 C6.1 C7.1 C8.1 C9.1 C10.1 C11.2 C12.1 C13.1 C14.2 C15.1 C16.1 C17.1 C19.1 C20.2 C21.2 C22.2 C24.2 C25.2 C26.2 C28.2 C29.2 C31.2 C32.2 C33.2 C34.2 C35.2 C36.2 C37.2 C38.2 C40.1 C41.2 C43.1 C44.1 C45.1 C46.2 C47.1 C48.1 C49.1 C51.2 C52.2 C53.2 C54.2 C56.1 C59.1 C60.1 C61.2 C62.2 C63.2 C64.2 C66.2 C67.2 C68.2 C70.2 C71.2 C73.1 C74.2 C75.1 C76.1 C77.2 C78.2 C79.2 C80.2 C81.2 C82.2 C83.2 C84.2 C85.2 C86.2 C87.2 C88.2 C89.2 C90.2 C91.1 C92.2 E7.1 E11.1 E12.1 E13.1(A) E14.1 J1.2 J1.3 J1.4 J1.5 J2.2 J2.3 J2.4 J2.5 J3.3 J3.8 J3.12 J3.13 J4.2 J4.3 J4.4 J4.5 J5.2 J5.10 JP1.3 P1.1 P1.3 P1.5 P1.6 P1.7 P1.9 P1.11 P1.12 P1.13 P1.15 P1.17 P1.18 P1.19 P1.21 P1.23 P1.24 P1.25 P1.27 P1.29 P1.30 P1.31 P1.33 P1.35 P1.36 P1.37 P1.39 P1.41 P1.42 P1.43 P1.45 P1.47 P1.48 P1.49 P1.51 P1.53 P1.54 P1.55 P1.57 P1.59 P1.60 P1.61 P1.63 P1.65 P1.66 P1.67 P1.69 P1.71 P1.72 P1.73 P1.75 P1.77 P1.78 P1.79 P1.81 P1.83 P1.84 P1.85 P1.89 P1.90 P1.95 P1.96 R5.2 R6.2 R17.1 R18.2 R20.1 R22.1 R24.1 R26.2 R29.2 R43.2 R54.2 R56.2 R80.1 R81.2 R87.2 R90.2 R93.2 RP1.9 TP4.1 TP6.1 TP7.1 U1.4(GND) U1.7(GND) U1.23(GND) U1.24(GND) U1.25(GND) U2.3 U3.2(D) U3.4(GND) U4.3 U6.3(GND) U7.1(A0) U7.2(A1) U7.3(A2) U7.4(VSS) U8.3 U9.3 U11.A1(GND) U11.A13(GND) U11.B8(GND) U11.C3(GND) U11.D2(ANAIN1) U11.D5(GND) U11.E2(REFGND) U11.E11(GND) U11.F3(GND) U11.G7(GND) U11.H12(GND) U11.J4(GND) U11.L9(GND) U11.M6(GND) U11.N1(GND) U11.N13(GND) U12.3(GND) U12.6(GND) U12.7(GND) U13.3(GND) U13.6(GND) U13.7(GND) U14.3(GND) U14.6(GND) U14.7(GND) U15.3(GND) U15.4(GND) U15.5(GND) U15.8(GND) U16.3(GND) U16.6(GND) U16.7(GND) U17.1(GND) U19.6(A0) U19.7(A1) U19.9(A2) U19.15(GND) U20.1(A) U20.3(GND)
SEL0/GND: R113.1 U1.11(GND/SEL0)
SEL1/GND: R60.1 U1.12(GND/SEL1)
VCCIO: C1.1 C2.1 C3.1 C4.1 C6.2 C7.2 C13.2 C15.2 C21.1 C26.1 C27.1 C41.1 C61.1 C62.1 C63.1 C64.1 C79.1 C80.1 C81.1 C82.1 C83.1 C84.1 C85.1 C86.1 C87.1 E1.1(A) J5.4 R2.1 R21.1 R25.1 R40.1 R92.1 R95.2 R96.2 R97.2 R100.1 U1.22(OVDD) U2.5 U3.6(~{CLR}) U3.8(VCC) U4.5 U6.5(VCC) U8.5 U9.5 U11.C6(VCCIO8) U11.C7(VCCIO8) U11.C8(VCCIO8) U11.F2(VCCIO1A) U11.F11(VCCIO6) U11.G3(VCCIO1B) U11.G11(VCCIO6) U11.H11(VCCIO5) U11.J3(VCCIO2) U11.J11(VCCIO5) U11.K3(VCCIO2) U11.L6(VCCIO3) U11.L7(VCCIO3) U11.L8(VCCIO3) U13.1(OUT) U19.5(VDD) U20.5(VCC)
VDD: C9.2 C10.2 C29.1 C30.1 E2.1(A) R19.1 U1.3(VDD) U14.1(OUT)
!DRDY: R7.1 TP5.1 U11.C1(IOC1)
B32_40_I2C: R16.1 U19.16(P4)
BUSY: R85.1 TP29.1 U11.B1(IOB1)
CLK: R3.2 TP30.1 U11.N2(ION2)
CLK_SYNC: P1.52 R23.1 TP16.1
CNVCLK: P1.50 R14.1 TP15.1
CONFIG_DONE: R95.1 TP9.1 U11.C5(IOC5)
CS2: R33.1 U19.12(P2)
CS_IN: R94.1 TP1.1 U19.20(P7)
D0: P1.100 R109.1
D1: P1.98 R108.1
D2: P1.94 R107.1
D3: P1.92 R106.1
D4: P1.88 R105.1
D5: P1.86 R104.1
D6: P1.82 R71.1
D7: P1.80 R103.1
D8: P1.76 R72.1
D9: P1.74 R102.1
D10: P1.70 R73.1
D11: P1.68 R101.1
D12: P1.64 R61.1
D13: P1.62 R62.1
D14: P1.58 R63.1
D15: P1.56 R64.1
D16: P1.46 R65.1
D17: P1.44 R66.1
D18: P1.40 R67.1
D19: P1.38 R68.1
D20: P1.34 R74.1
D21: P1.32 R75.1
D22: P1.28 R76.1
D23: P1.26 R77.1
D24: P1.22 R78.1
D25: P1.20 R84.1
D26: P1.16 R79.1
D27: P1.14 R69.1
D28: P1.10 R70.1
D29: P1.8 R82.1
D30: P1.4 R27.1
D31: P1.2 R31.1
J3-2: J3.2 R13.1
MCLK: J3.6 TP28.1 U1.13(MCLK) U6.2(B) U11.L4(IOL4)
MCLKL_33: R83.1 TP17.1 U4.2
nCONFIG: R97.1 TP10.1 U11.E7(IOE7)
nSTATUS: R96.1 TP8.1 U11.C4(IOC4)
PRE: R57.1 U20.4(OE)
QuikEval_DETECT: U6.4(OE) U9.4 U11.D1(IOD1)
RDLA: R32.1 TP22.1 U1.1(RDLA)
RDLB: R89.1 TP21.1 U1.2(RDLB)
SCK2: R112.1 U19.10(P0)
SCK_IN: R58.1 TP3.1 U19.17(P5)
SCKA: J3.4 R110.1 TP25.1 U1.18(SCKA)
SCKB: R111.1 TP26.1 U1.19(SCKB)
SCL: J3.11 P1.87 R11.2 TP19.1 U7.6(SCL) U19.2(SCL)
SDA: J3.9 P1.91 R12.2 TP18.1 U7.5(SDA) U19.4(SDA)
SDI: J3.7 R99.1 TP27.1 U1.16(SDI/GND)
SDI2: R38.2 U19.11(P1)
SDI_IN: R98.1 TP2.1 U19.19(P6)
SDOA: J3.5 R91.2 TP23.1 U11.J1(IOJ1)
SDOB: R59.1 TP24.1 U11.M1(IOM1)
SYNC: J3.14 R49.1 TP20.1 U1.14(SYNC)
TCK: J5.1 R24.2 TP14.1 U11.G2(IOG2)
TDI: J5.9 TP11.1 U11.F5(IOF5)
TDO: J5.3 TP13.1 U11.F6(IOF6)
TMS: J5.5 R21.2 TP12.1 U11.G1(IOG1)
V+: C40.2 C42.2 C45.2 C47.2 C48.2 C49.2 C50.1 C52.1 C55.2 C57.2 C58.2 C88.1 E4.1(A) R42.1 U5.5(V+) U10.7(V+) U16.1(OUT) U18.7(V+) U21.3(V+) U21.7(!SHDN)
V-: C17.2 C19.2 C42.1 C43.2 C44.2 C53.1 C55.1 C57.1 C58.1 C77.1 C89.1 E9.1(A) R28.1 U5.2(V-) U10.4(V-) U17.5(OUT) U18.4(V-) U21.6(V-)
VREF: C20.1 C56.2 C92.1 E3.1(A) R37.2 R41.2 R86.1 U1.8(REF)
VREF/2: C59.2 C60.2 JP4.2 R35.2 R36.1 U21.2(VOCM)
WRIN_I2C: R34.1 U19.14(P3)
N372319: U1.9(REF) U15.6(VOUTS)
N372559: C46.1 R37.1 U15.7(VOUTF)
N16992293: C71.1 C72.1 C90.1 R9.1 R46.2 R48.2
N16993212: C72.2 C73.2 C91.2 R4.1 R50.2 R51.2
N17061773: C8.2 JP4.1 R18.1 R88.2
N17117998: C74.1 E5.1(A) JP4.3
N17160985: J2.1 R55.1
N17161039: C18.1 C67.1 JP5.2 R53.2
N17161043: C18.2 C68.1 JP5.1 R35.1 R44.2 R54.1 RP1.2
N17161106: J4.1 R53.1
N17185612: C69.1 C70.1 JP2.2 R55.2
N17185667: C66.1 C69.2 JP2.1 R36.2 R52.1 R56.1 RP1.3
N17319496: C76.2 R44.1 R45.1 U10.3(+IN)
N17319914: C65.2 R45.2 R48.1 R114.2 RP1.1 U10.6(OUT) U21.5(-OUT)
N17324569: C65.1 R46.1 R114.1 U10.2(-IN)
N17467852: C75.2 R47.1 R52.2 U18.3(+IN)
N17468719: C39.2 R30.2 R47.2 R51.1 RP1.4 U18.6(OUT) U21.4(+OUT)
N17487551: C39.1 R30.1 R50.1 U18.2(-IN)
N17967756: C14.1 J3.10 P1.93 R10.1 R11.1 R12.1 U7.8(VCC)
N17967760: JP1.2 R10.2 U7.7(WP)
N18060851: C5.2 R2.2 R6.1 U8.2
N18060871: C5.1 J1.1 R5.1
N18060885: R1.2 U2.2 U8.4
N18064319: R1.1 U3.1(CP)
N18064359: R15.2 U3.7(~{PR})
N18064415: R15.1 U4.4
N18066762: R8.1 U6.1(A)
N18548220: P1.99 R80.2
N18555793: P1.97 R100.2
N18790437: C16.2 R13.2 R17.2 U9.2
N18989565: C78.1 R86.2 R87.1 U5.3(+IN)
N18998015: R88.1 U5.1(OUT) U5.4(-IN)
N19413439: R42.2 R43.1 U16.2(SENSE/ADJ)
N19413481: C50.2 U16.4(BYP)
N19414430: R28.2 R29.1 U17.4(ADJ)
N19415155: C23.2 U12.4(BYP)
N19416278: C27.2 U13.4(BYP)
N19416288: JP3.2 R25.2 R26.1 U13.2(SENSE/ADJ)
N19417518: C30.2 U14.4(BYP)
N19418791: R19.2 R90.1 U14.2(SENSE/ADJ)
N19440942: R7.2 U1.15(~{DRDY})
N19524664: R92.2 R93.1 U11.D7(IOD7)
N19598042: R14.2 U11.H13(IOH13)
N19598058: R71.2 U11.L13(IOL13)
N19598074: R103.2 U11.L12(IOL12)
N19598090: R73.2 U11.K12(IOK12)
N19598106: R101.2 U11.K11(IOK11)
N19598128: R61.2 U11.K10(IOK10)
N19598152: R62.2 U11.J13(IOJ13)
N19598156: R63.2 U11.J12(IOJ12)
N19598178: R64.2 U11.J10(IOJ10)
N19598198: R65.2 U11.H10(IOH10)
N19598202: R66.2 U11.G13(IOG13)
N19598218: R67.2 U11.G12(IOG12)
N19598557: R79.2 U11.C12(IOC12)
N19598559: R69.2 U11.C11(IOC11)
N19598603: R76.2 U11.E10(IOE10)
N19598605: R77.2 U11.D11(IOD11)
N19598607: R78.2 U11.D12(IOD12)
N19598615: R84.2 U11.C13(IOC13)
N19598639: R82.2 U11.B13(IOB13)
N19598641: R23.2 U11.G10(IOG10)
N19598657: R27.2 U11.B12(IOB12)
N19598673: R31.2 U11.A12(IOA12)
N19598701: R68.2 U11.F12(IOF12)
N19598705: R74.2 U11.F10(IOF10)
N19598721: R75.2 U11.E12(IOE12)
N19599024: R83.2 U11.H4(IOH4)
N19599064: R111.2 U11.M2(IOM2)
N19599070: R99.2 U11.L2(IOL2)
N19599094: R110.2 U11.J2(IOJ2)
N19599108: R94.2 U11.M3(IOM3)
N19599276: R70.2 U11.C10(IOC10)
N19599278: R32.2 U11.A2(IOA2)
N19599294: R89.2 U11.B2(IOB2)
N19600172: R109.2 U11.N12(ION12)
N19600188: R108.2 U11.N10(ION10)
N19600204: R107.2 U11.M13(IOM13)
N19600220: R106.2 U11.M12(IOM12)
N19600236: R105.2 U11.M11(IOM11)
N19600260: R104.2 U11.M10(IOM10)
N19600268: R72.2 U11.L11(IOL11)
N19600284: R102.2 U11.L10(IOL10)
N19600300: R98.2 U11.N6(ION6)
N19600313: R58.2 U11.N7(ION7)
N19600326: R16.2 U11.M9(IOM9)
N19600339: R34.2 U11.N4(ION4)
N19600352: R33.2 U11.M4(IOM4)
N19600366: R38.1 U11.M5(IOM5)
N19600376: R112.2 U11.N9(ION9)
N19608334: R20.2 U11.N3(ION3)
N19609671: R22.2 U11.F9(IOF9)
N19681355: J3.1 R39.1
N20033214: R40.2 U11.E5(IOE5)
N20047988: C12.2 R41.1 U1.10(PRE/REF) U20.2(B)
N20048737: R8.2 U3.3(~{Q})
N20180175: R49.2 U11.E3(IOE3)
N20180189: R57.2 U11.E4(IOE4)
N20180287: R113.2 U11.F1(IOF1)
N20180297: R60.2 U11.E1(IOE1)
N20339164: TP32.1 U11.A8(IOA8)
N20339167: TP33.1 U11.A7(IOA7)
N20339170: TP34.1 U11.A6(IOA6)
N20339173: TP35.1 U11.A5(IOA5)
N20339176: TP36.1 U11.A4(IOA4)
N20339179: TP37.1 U11.A3(IOA3)
N20339182: TP38.1 U11.B3(IOB3)
N20339185: TP31.1 U11.A9(IOA9)
N20449841: R91.1 U1.17(SDOA)
N20450121: R85.2 U1.21(BUSY)
N20450249: R9.2 U1.5(IN+)
N20500476: RP1.5 RP1.6 U21.1(-IN)
N20500558: RP1.7 RP1.8 U21.8(+IN)
N20577894: R59.2 U1.20(SDOB)
N20709030: R4.2 U1.6(IN-)
N20862768: JP3.3 R81.1
N20897711: R3.1 U2.4

Not connected (* = marked no-connect by the designer): J5 6* 7* 8*; JP1 1; JP2 3; JP3 1*; JP5 3; U3 5(Q)*; U10 1* 5* 8*; U11 A10(IOA10)* A11(IOA11)* B4(IOB4)* B5(IOB5)* B6(IOB6)* B7(IOB7)* B9(IOB9)* B10(IOB10)* B11(IOB11)* C2(IOC2)* C9(IOC9)* D6(IOD6)* D8(IOD8)* D9(IOD9)* D13(IOD13)* E6(IOE6)* E8(IOE8)* E9(IOE9)* E13(IOE13)* F4(IOF4)* F8(IOF8)* F13(IOF13)* G4(IOG4)* G5(IOG5)* G9(IOG9)* H1(IOH1)* H2(IOH2)* H3(IOH3)* H5(IOH5)* H6(IOH6)* H8(IOH8)* H9(IOH9)* J5(IOJ5)* J6(IOJ6)* J7(IOJ7)* J8(IOJ8)* J9(IOJ9)* K1(IOK1)* K2(IOK2)* K5(IOK5)* K6(IOK6)* K7(IOK7)* K8(IOK8)* K13(IOK13)* L1(IOL1)* L3(IOL3)* L5(IOL5)* M7(IOM7)* M8(IOM8)* N5(ION5)* N8(ION8)* N11(ION11)*; U18 1* 5* 8*; U19 1(\\~{INT})* 3(NC)* 8(NC)* 13(NC)* 18(NC)*

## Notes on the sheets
sheet 1
- +9V/+10V
- V+
- GND
- GND
- V-
- -9V / -10V
- GND
- VCCIO
- VCCI0
- +2.5V
- +3.3V
- GND
- PCA ADDITIONAL PARTS
- VDD
- NOTES:
- 1. ALL RESISTORS AND CAPACITORS THIS PAGE ARE SIZE 0603 UNLESS OTHERWISE NOTED.
- +3.3V
- OVERSAMPLED 32-BIT ADC
- WITH PROGRAMMABLE DIGITAL FILTER
- -
- Tuesday, November 01, 2016
- -
sheet 2
- BYPASS CAPS FOR U11
- VCC_ONE
- JTAGEN
- VCCIO8
- VCCIO6
- JTAG
- MCLKL_33
- VCC_A4-A1
- VCCIO3
- CNVCLK
- CLK_SYNC
- TCK
- VCCIO1A,B
- VCCIO2
- VCCIO5
- TDO
- TMS
- TDI
- CS_IN
- Address
- SDI_IN
- 40H Write
- 41H Read
- SDA
- SCK_IN
- SCL
- TM
- QuikEval
- (D6= CRC_ERROR)
- P6
- P2
- WP
- P7
- P1
- EEPROM
- PROG
- Address
- P0
- A0H Write
- A1H Read
- (B9= DEV_CLRn)
- (D8= DEV_OE)
- NOTES:
- P3
- 1. ALL RESISTORS AND CAPACITORS THIS PAGE ARE SIZE 0402 UNLESS OTHERWISE NOTED.
- P5
- P4
- OVERSAMPLED 32-BIT ADC
- WITH PROGRAMMABLE DIGITAL FILTER
- -
- Tuesday, November 01, 2016
sheet 3
- CLK IN
- 100MHz MAX
- 3.3VPP
- CLK
- COUPLING
- VREF
- AC
- DC
- GND
- AIN+
- 0 - VREF
- BUSY
- MCLK
- CM
- VREF/2
- EXT
- EXT_CM
- SDOA
- SDOB
- SCKA
- SCKB
- COUPLING
- SYNC
- AC
- DC
- AIN-
- GND
- 0 - VREF
- RDLB
- GND
- RDLA
- !DRDY
- GND
- NOTES:
- SDI/GND
- BYPASS CAPS FOR U18
- BYPASS CAPS FOR U10
- 1. ALL RESISTORS AND CAPACITORS THIS PAGE ARE SIZE 0603 UNLESS OTHERWISE NOTED.
- *
- ASSEMBLY OPTIONS
- LTC SKU#
- U1 USED
- BITS
- fs max (ksps)
- PIN 10
- PIN 11
- PIN 12
- PIN 16
- DC2222A-A
- LTC2500-IDKD-32
- 32
- 1000
- PRE
- GND
- GND
- SDI
- DC2222A-B
- LTC2508-IDKD-32
- 32
- 3.9
- REF
- SEL0
- SEL1
- GND
- DC2222A-C
- LTC2512-IDKD-24
- 24
- 400
- REF
- SEL0
- SEL1
- GND
- OVERSAMPLED 32-BIT ADC
- WITH PROGRAMMABLE DIGITAL FILTER
- -
- Tuesday, November 01, 2016
